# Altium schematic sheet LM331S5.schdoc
size 127 x 101 mm
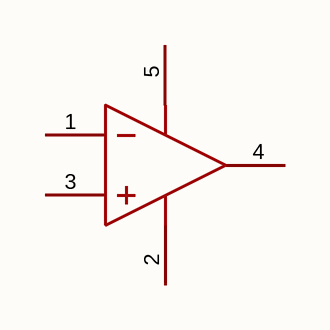
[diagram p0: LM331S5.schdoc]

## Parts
U?  lm331s5  [SOT-23-5_L2.9-W1.6-P0.95-LS2.8-BR]  (value not drawn)

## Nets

Not connected (* = marked no-connect by the designer): U? 1(IN-) 2(GND) 3(IN+) 4(OUT) 5(VCC)

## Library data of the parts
U? = lm331s5: Manufacturer: TECH PUBLIC(台舟); AddInBom: yes; ModelId: 7ba65df16e7b4570af156e925f9c37fe; ModelTransform: 114.173,114.173,0,90,0,0,0,0,0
